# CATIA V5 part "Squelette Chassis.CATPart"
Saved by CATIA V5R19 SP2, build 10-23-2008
Part number: Squelette Chassis
Bounding box of the stored display mesh (mm): x 8 to 400, y -38 to 38, z 5.491 to 44.162
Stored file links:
  E:\Mes documents\03_Ressources pédagogiques\01_Catia\Buggy Dassault\SchemaCinematiqueFinal\Squelette Chassis.CATPart
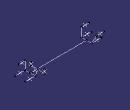
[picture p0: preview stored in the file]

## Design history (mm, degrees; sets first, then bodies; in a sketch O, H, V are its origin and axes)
AxisSystem1: origin (0, 0, 0), X (1, 0, 0), Y (0, 1, 0), Z (0, 0, 1)
Body1 (main body)
  Line1 to Line9: stored without definition
  Point1 to Point4: stored without definition
  Line10: stored without definition
  Line11: stored without definition
  Point5: stored without definition
  MultiSel1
